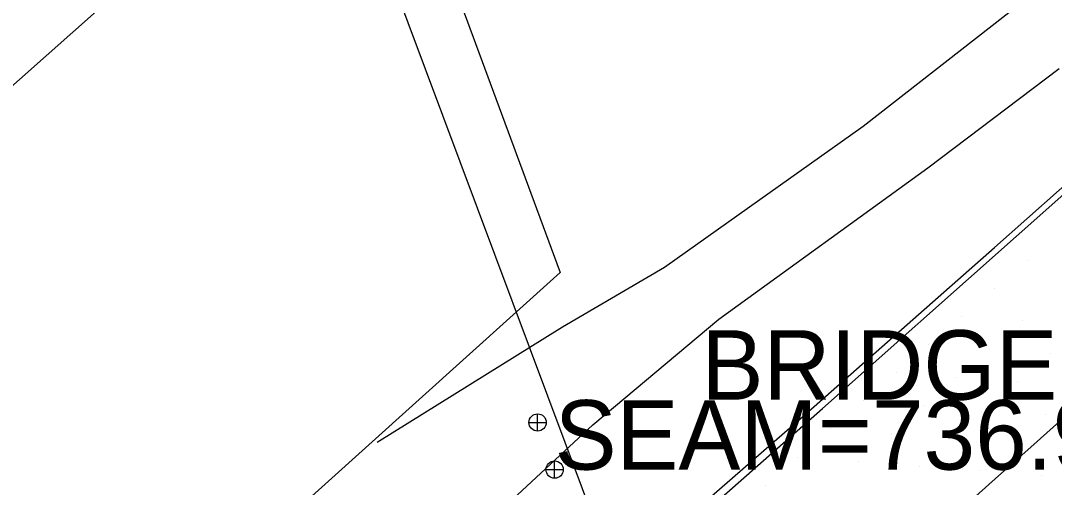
# Model space of a CAD drawing. Extents: x 1548934 to 1561348, y 809680 to 824075.
# Drawn here: x 1551780.7 to 1551840.5, y 810812.5 to 810839.5 of the extents above; entities that cross this region are included whole.
import ezdxf

# ---------------------------------------------------------------- set-up
doc = ezdxf.new("R2010")
doc.units = 0
for name, color, linetype in [('Default', 7, 'Continuous'), ('E_NCDOT_Vertical_Profile_Ground_Line', 7, 'Continuous'), ('Exist DTM Scan Elevation Point', 7, 'Continuous'), ('Exist Guardrail', 7, 'Continuous'), ('Exist Structure Major Bridge Seam Top Elevation', 7, 'Continuous'), ('Exist Structure Major Deck Tunnel Box Culvert', 7, 'Continuous'), ('P_RDY_Paved_Shoulder', 7, 'Continuous'), ('P_RDY_Terminator_Cell', 7, 'Continuous'), ('PH Exist DTM Breakline', 7, 'Continuous')]:
    doc.layers.add(name, color=color, linetype=linetype)

# ---------------------------------------------------------------- blocks, each defined once
blk = doc.blocks.new('SurveyPointCell')
at = {"layer": 'Default'}
for p, q in [((-0.5, 0), (0.5, 0)), ((0, -0.5), (0, 0.5))]:
    blk.add_line(p, q, dxfattribs=at)
blk.add_circle((0, 0), 0.5, dxfattribs=at)

msp = doc.modelspace()

# ---------------------------------------------------------------- linework, layer by layer
at = {"layer": 'E_NCDOT_Vertical_Profile_Ground_Line'}
msp.add_lwpolyline([(1551623.114, 810640.529), (1551645.931, 810660.005), (1551668.609, 810679.564), (1551691.2, 810699.178), (1551713.871, 810718.824), (1551736.487, 810738.534), (1551759.39, 810757.969), (1551782.045, 810777.634), (1551804.648, 810797.259), (1551827.112, 810817.056), (1551849.55, 810836.968), (1551871.85, 810857.001), (1551894.133, 810877.042), (1551916.371, 810897.058), (1551938.535, 810917.275)], dxfattribs=at)
at = {"layer": 'Exist DTM Scan Elevation Point'}
for p, q in [((1551838.957, 810825.642), (1551838.957, 810825.642)), ((1551837.06, 810824.014), (1551837.06, 810824.014)), ((1551835.164, 810822.385), (1551835.164, 810822.385)), ((1551838.689, 810822.117), (1551838.689, 810822.117)), ((1551833.267, 810820.756), (1551833.267, 810820.756)), ((1551836.792, 810820.488), (1551836.792, 810820.488)), ((1551840.317, 810820.22), (1551840.317, 810820.22)), ((1551831.371, 810819.127), (1551831.371, 810819.127)), ((1551834.896, 810818.859), (1551834.896, 810818.859)), ((1551838.421, 810818.591), (1551838.421, 810818.591)), ((1551829.475, 810817.498), (1551829.475, 810817.498)), ((1551833, 810817.23), (1551833, 810817.23)), ((1551836.524, 810816.962), (1551836.524, 810816.962)), ((1551840.05, 810816.694), (1551840.05, 810816.694)), ((1551827.578, 810815.869), (1551827.578, 810815.869)), ((1551831.103, 810815.601), (1551831.103, 810815.601)), ((1551834.628, 810815.333), (1551834.628, 810815.333)), ((1551838.153, 810815.065), (1551838.153, 810815.065)), ((1551825.682, 810814.24), (1551825.682, 810814.24)), ((1551829.207, 810813.972), (1551829.207, 810813.972)), ((1551832.732, 810813.704), (1551832.732, 810813.704)), ((1551836.257, 810813.436), (1551836.257, 810813.436)), ((1551839.782, 810813.169), (1551839.782, 810813.169)), ((1551823.786, 810812.611), (1551823.786, 810812.611))]:
    msp.add_line(p, q, dxfattribs=at)
at = {"layer": 'Exist Guardrail'}
msp.add_lwpolyline([(1551757.983, 810757.324), (1551769.38, 810767.068), (1551780.686, 810776.926), (1551791.953, 810786.827), (1551803.251, 810796.694), (1551814.514, 810806.594), (1551825.811, 810816.461), (1551837.07, 810826.37), (1551848.296, 810836.318), (1551859.509, 810846.279), (1551870.676, 810856.292), (1551881.798, 810866.357), (1551892.982, 810876.353), (1551904.137, 810886.38), (1551915.273, 810896.429), (1551926.283, 810906.614), (1551937.333, 810916.757), (1551948.379, 810926.903), (1551959.351, 810937.132), (1551970.296, 810947.379), (1551981.198, 810957.682), (1551992.011, 810968.086), (1552001.046, 810976.727), (1552002.786, 810977.64)], dxfattribs=at)
at = {"layer": 'Exist Structure Major Deck Tunnel Box Culvert'}
msp.add_lwpolyline([(1551890.16, 810628.772), (1551869.489, 810674.52), (1551854.065, 810710.393), (1551839.842, 810744.541), (1551817.227, 810801.667), (1551801.118, 810844.761), (1551789.242, 810877.577)], dxfattribs=at)
at = {"layer": 'P_RDY_Paved_Shoulder'}
for points in [[(1551780.343, 810801.61), (1551763.58, 810848.598), (1551777.948, 810861.189), (1551793.414, 810875.004), (1551811.927, 810824.916)], [(1551811.927, 810824.916), (1551795.394, 810810.049), (1551782.457, 810799.025), (1551778.178, 810796.314), (1551771.085, 810790.716)]]:
    msp.add_lwpolyline(points, dxfattribs=at)
at = {"layer": 'P_RDY_Terminator_Cell'}
for points in [[(1551800.593, 810853.787), (1551785.249, 810840.199), (1551771.505, 810828.032)], [(1551835.432, 810811.483), (1551837.301, 810813.144), (1551839.169, 810814.805), (1551841.037, 810816.467)]]:
    msp.add_lwpolyline(points, dxfattribs=at)
at = {"layer": 'PH Exist DTM Breakline'}
for points in [[(1551976.063, 810969.117), (1551949.262, 810946.008), (1551929.742, 810928.027), (1551906.224, 810905.666), (1551886.676, 810885.568), (1551862.451, 810861.533), (1551842.48, 810843.549), (1551829.474, 810833.372), (1551817.96, 810825.212), (1551812.063, 810821.762), (1551801.327, 810815.073)], [(1551623.76, 810648.551), (1551656.195, 810677.073), (1551677.461, 810694.698), (1551698.697, 810712.408), (1551715.857, 810726.522), (1551742.572, 810749.311), (1551752.288, 810758.175), (1551762.621, 810768.49), (1551773.345, 810779.04), (1551777.174, 810783.436), (1551784.866, 810789.211), (1551813.809, 810816.109), (1551821.1, 810822.214), (1551833.215, 810830.987), (1551840.823, 810836.732)]]:
    msp.add_lwpolyline(points, dxfattribs=at)

# ---------------------------------------------------------------- block references
at = {"layer": 'Default'}
for p in [(1551810.615, 810816.242), (1551811.6, 810813.513)]:
    msp.add_blockref('SurveyPointCell', p, dxfattribs=at)

# ---------------------------------------------------------------- texts
at = {"layer": 'Exist Structure Major Bridge Seam Top Elevation'}
for s, p in [('BRIDGE', (1551820.108, 810817.56)), ("SEAM=736.94''", (1551811.6, 810813.513))]:
    msp.add_text(s, height=4.02, dxfattribs=at).set_placement(p)

doc.saveas('drawing.dxf')
